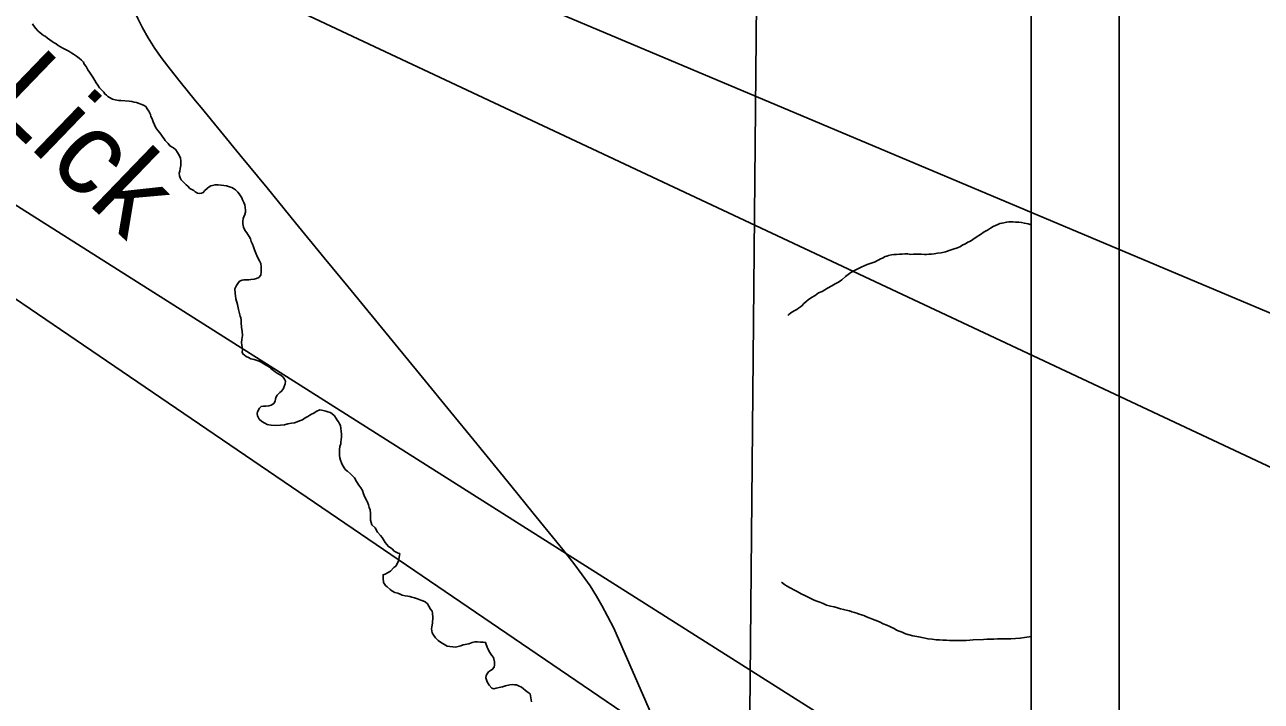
# Model space of a CAD drawing. Extents: x 0 to 34, y 0 to 22.
# Drawn here: x 7.757 to 9.161, y 15.487 to 16.256 of the extents above; entities that cross this region are included whole.
import ezdxf

# ---------------------------------------------------------------- set-up
doc = ezdxf.new("R2010")
doc.units = 0
for name, color, linetype in [('GM_X_County_Text', 7, 'Continuous'), ('GM_X_Minor_River', 7, 'Continuous'), ('GM_X_Minor_River_Text', 7, 'Continuous'), ('GM_X_Rail_Line_Text', 7, 'Continuous'), ('GM_X_State_Route', 7, 'Continuous'), ('SH_Cut_Line', 7, 'Continuous'), ('SH_Data', 7, 'Continuous'), ('TX_P_1', 7, 'Continuous')]:
    doc.layers.add(name, color=color, linetype=linetype)

msp = doc.modelspace()

# ---------------------------------------------------------------- linework, layer by layer
at = {"layer": 'GM_X_County_Text'}
msp.add_lwpolyline([(6.615, 14.1), (8.9, 14.1), (8.9, 16.3981)], dxfattribs=at)
at = {"layer": 'GM_X_Minor_River'}
for points in [[(7.7657, 16.2566), (7.7668, 16.2547), (7.7694, 16.2516), (7.7723, 16.2485), (7.7742, 16.2469), (7.7764, 16.245), (7.7783, 16.2434), (7.7802, 16.2426), (7.7828, 16.2406), (7.788, 16.2367), (7.7902, 16.2351), (7.7925, 16.2339), (7.7947, 16.232), (7.7977, 16.2308), (7.8, 16.2292), (7.8026, 16.228), (7.8048, 16.2268), (7.8071, 16.2256), (7.8105, 16.2233), (7.8123, 16.2224), (7.8157, 16.2201), (7.8187, 16.2177), (7.8213, 16.2154)], [(7.8213, 16.2154), (7.8235, 16.2131), (7.8246, 16.2111), (7.8268, 16.2081), (7.8286, 16.2046), (7.8305, 16.2019), (7.8319, 16.1996), (7.8341, 16.1961), (7.8367, 16.1922), (7.8381, 16.1899), (7.84, 16.1872), (7.8418, 16.1841), (7.8437, 16.1822), (7.8466, 16.1791), (7.8477, 16.1772), (7.8496, 16.1756), (7.8514, 16.174), (7.8533, 16.1732), (7.8567, 16.1713), (7.8597, 16.1704), (7.8635, 16.1696), (7.8661, 16.1695), (7.8756, 16.1689), (7.8786, 16.1685), (7.8813, 16.1676), (7.8839, 16.1672), (7.8869, 16.1664), (7.8888, 16.1656), (7.8918, 16.1643), (7.8945, 16.1628), (7.8959, 16.1601), (7.8977, 16.1574), (7.8996, 16.1539), (7.9003, 16.1516), (7.9014, 16.1497), (7.9021, 16.1478), (7.9028, 16.1455), (7.9042, 16.142), (7.906, 16.1386), (7.9082, 16.1355), (7.9104, 16.1328), (7.9123, 16.1304), (7.9138, 16.1281), (7.9152, 16.1262), (7.9163, 16.1243), (7.9197, 16.1208), (7.9219, 16.118), (7.926, 16.1157), (7.9286, 16.1137), (7.9304, 16.1106), (7.9326, 16.1068), (7.9337, 16.1041), (7.9344, 16.101), (7.9343, 16.098), (7.9343, 16.0957), (7.9334, 16.0923), (7.933, 16.0893), (7.9325, 16.087), (7.9328, 16.084), (7.9335, 16.0817), (7.9346, 16.0794), (7.9372, 16.0767), (7.9402, 16.0739), (7.9421, 16.0724), (7.9446, 16.0696), (7.9469, 16.0684), (7.9488, 16.0673), (7.9506, 16.0657), (7.9533, 16.0645), (7.9555, 16.0641), (7.9578, 16.0644), (7.9597, 16.0651), (7.9613, 16.0673), (7.9644, 16.0699), (7.9663, 16.0714), (7.9683, 16.0725), (7.9702, 16.0732), (7.9732, 16.0739), (7.9766, 16.0738), (7.98, 16.0734), (7.9831, 16.0729), (7.9861, 16.0725), (7.9895, 16.0716), (7.9921, 16.0708), (7.994, 16.0696), (7.9962, 16.068), (7.9988, 16.0653), (8.0003, 16.0634), (8.0036, 16.0591), (8.0043, 16.0568), (8.0058, 16.0538), (8.0069, 16.0511), (8.0072, 16.048), (8.0078, 16.045), (8.0078, 16.0427), (8.007, 16.04), (8.0058, 16.0374), (8.005, 16.0355), (8.0045, 16.0325), (8.0048, 16.0295), (8.0055, 16.0256)], [(8.6242, 15.9252), (8.6246, 15.9259), (8.627, 15.9285), (8.6308, 15.9307), (8.6339, 15.9322), (8.6358, 15.9336), (8.6381, 15.9351), (8.6401, 15.9366), (8.642, 15.9388), (8.6443, 15.941), (8.647, 15.9432), (8.6505, 15.9458), (8.6547, 15.948), (8.6586, 15.9509), (8.6628, 15.9527), (8.6659, 15.9546), (8.6686, 15.9564), (8.6736, 15.9589), (8.6775, 15.9611), (8.6813, 15.9633), (8.6852, 15.9659), (8.6894, 15.9696), (8.6952, 15.974), (8.7018, 15.9777), (8.7071, 15.9802), (8.7106, 15.9816), (8.714, 15.9831), (8.7228, 15.9863), (8.7248, 15.9874), (8.7271, 15.9885), (8.729, 15.9896), (8.7313, 15.9906), (8.7344, 15.9925), (8.7363, 15.9928), (8.7382, 15.9935), (8.7413, 15.9942), (8.7443, 15.9945), (8.7473, 15.9948), (8.7504, 15.9951), (8.7534, 15.9951), (8.7568, 15.9954), (8.7599, 15.9953), (8.7629, 15.9948), (8.7663, 15.9951), (8.7694, 15.9951), (8.772, 15.995), (8.7751, 15.9949), (8.7788, 15.9948), (8.7811, 15.9948), (8.7838, 15.9951), (8.7868, 15.995), (8.7899, 15.9953), (8.7937, 15.996), (8.7979, 15.9967), (8.8028, 15.9977), (8.8082, 15.9995), (8.8128, 16.0009), (8.8166, 16.0023), (8.8197, 16.0037), (8.8224, 16.0056), (8.8254, 16.0066), (8.8281, 16.0085), (8.8312, 16.0099), (8.8339, 16.0118), (8.8378, 16.0143), (8.8424, 16.0173), (8.8466, 16.0202), (8.8505, 16.0224), (8.854, 16.0246), (8.857, 16.0264), (8.8597, 16.0275), (8.8624, 16.0286), (8.8647, 16.0297), (8.867, 16.0304), (8.8723, 16.0314), (8.8746, 16.0317), (8.8769, 16.0316), (8.8792, 16.0316), (8.8822, 16.0315), (8.886, 16.0314), (8.889, 16.031), (8.8924, 16.0301), (8.8966, 16.0293), (8.9, 16.0283)], [(8.0055, 16.0256), (8.0062, 16.0237), (8.0077, 16.021), (8.0091, 16.0191), (8.0102, 16.0172), (8.0117, 16.0149), (8.0132, 16.0126), (8.0142, 16.0095), (8.0157, 16.0064), (8.0167, 16.0034), (8.0178, 15.9999), (8.0196, 15.9961), (8.0214, 15.9915), (8.0236, 15.9876), (8.025, 15.9845), (8.0253, 15.9807), (8.0253, 15.9781), (8.0256, 15.975), (8.0251, 15.9712), (8.0227, 15.9683), (8.0201, 15.9672), (8.0174, 15.9665), (8.0136, 15.9662), (8.0113, 15.9659), (8.0079, 15.9659), (8.006, 15.966), (8.0037, 15.9653), (8.001, 15.9642), (7.9991, 15.9616), (7.9975, 15.9594), (7.9955, 15.9556), (7.9958, 15.9507), (7.9967, 15.9442), (7.9985, 15.9377), (7.9999, 15.9323), (8.0009, 15.9277), (8.0016, 15.9247), (8.0023, 15.9228), (8.0026, 15.9201), (8.0029, 15.9171), (8.0032, 15.9121), (8.0035, 15.9094), (8.0039, 15.9075), (8.0041, 15.9026), (8.0036, 15.898), (8.0032, 15.8946), (8.0035, 15.8916), (8.0038, 15.8893), (8.0041, 15.8866), (8.004, 15.8836), (8.0048, 15.8817), (8.0085, 15.8786), (8.0111, 15.8774), (8.0137, 15.8761), (8.0175, 15.8753), (8.0232, 15.8733), (8.0254, 15.8721), (8.0277, 15.8709), (8.031, 15.8689), (8.0329, 15.8677), (8.0348, 15.8665), (8.0366, 15.865), (8.0396, 15.8626), (8.0415, 15.8614), (8.0437, 15.8599), (8.0456, 15.8587), (8.0479, 15.8575), (8.0505, 15.8551), (8.0519, 15.8528), (8.053, 15.8505), (8.0526, 15.8475), (8.0517, 15.8445), (8.0509, 15.8422), (8.0486, 15.8392), (8.0466, 15.8378), (8.0435, 15.8348), (8.0423, 15.8322), (8.0419, 15.8303), (8.0415, 15.828), (8.0399, 15.8254), (8.0368, 15.8232), (8.0341, 15.8225), (8.0307, 15.8222), (8.028, 15.8222), (8.0254, 15.8219), (8.0234, 15.8201), (8.0214, 15.8159), (8.021, 15.814), (8.0213, 15.8114), (8.0231, 15.8075), (8.0261, 15.8048), (8.0295, 15.8028), (8.0321, 15.8016), (8.034, 15.8012), (8.037, 15.8008), (8.0419, 15.8003), (8.0473, 15.8005), (8.0518, 15.8012), (8.0557, 15.8022), (8.0599, 15.8029), (8.0633, 15.8035)], [(8.0633, 15.8035), (8.0663, 15.8046), (8.069, 15.8057), (8.0725, 15.8068), (8.0756, 15.809), (8.0786, 15.8104), (8.0806, 15.8119), (8.0825, 15.813), (8.0844, 15.8141), (8.0887, 15.8166), (8.0921, 15.8181), (8.0959, 15.8172), (8.0989, 15.8164), (8.1012, 15.8159), (8.1038, 15.8151), (8.1057, 15.8139), (8.1086, 15.8112), (8.1108, 15.8081), (8.1119, 15.8062), (8.1134, 15.8043), (8.1145, 15.8023), (8.1156, 15.8004), (8.1169, 15.7905), (8.1168, 15.7875), (8.1164, 15.7841), (8.1159, 15.7818), (8.1159, 15.7795), (8.115, 15.7765), (8.1146, 15.7731), (8.1145, 15.7693), (8.1144, 15.7662), (8.1147, 15.7636), (8.1154, 15.7609), (8.1169, 15.7578), (8.1176, 15.7559), (8.1198, 15.7521), (8.1216, 15.7497), (8.1235, 15.7482), (8.1268, 15.7454), (8.1291, 15.7431), (8.1313, 15.7408), (8.1338, 15.7365), (8.1364, 15.7323), (8.1386, 15.7296), (8.1404, 15.7265), (8.1419, 15.7227), (8.1426, 15.7207), (8.1437, 15.7181), (8.1451, 15.7154), (8.1462, 15.7131), (8.1473, 15.71), (8.1483, 15.7069), (8.1494, 15.7046), (8.1497, 15.7001), (8.1496, 15.6959), (8.1495, 15.6928), (8.1513, 15.6875), (8.155, 15.684), (8.1575, 15.679), (8.1609, 15.6751), (8.1631, 15.6731), (8.1664, 15.6674), (8.1701, 15.6627), (8.1742, 15.6603), (8.1764, 15.6576), (8.1809, 15.6552), (8.1828, 15.6548), (8.1827, 15.6525), (8.1814, 15.6461), (8.1783, 15.6405), (8.176, 15.639), (8.1725, 15.6349), (8.169, 15.6327), (8.1663, 15.6313), (8.164, 15.6306), (8.1639, 15.6268), (8.1646, 15.6218), (8.1667, 15.6183), (8.1686, 15.6168), (8.172, 15.614), (8.1738, 15.6125), (8.1772, 15.6105), (8.1806, 15.6097), (8.1832, 15.6085), (8.1858, 15.6073), (8.1889, 15.6068), (8.1919, 15.6064), (8.1945, 15.6059), (8.1968, 15.6051), (8.1998, 15.6043), (8.2032, 15.6034), (8.2051, 15.6026), (8.207, 15.6018), (8.2092, 15.601), (8.2119, 15.5998), (8.2145, 15.5975), (8.2159, 15.5951), (8.2177, 15.5917), (8.2196, 15.5894), (8.2199, 15.5871), (8.2206, 15.5821)], [(8.6167, 15.6221), (8.6201, 15.6194), (8.6223, 15.6182), (8.6257, 15.6162), (8.6279, 15.615), (8.6305, 15.6135), (8.6343, 15.6115), (8.6388, 15.6091), (8.6429, 15.6071), (8.6538, 15.6019), (8.6568, 15.6007), (8.6602, 15.5995), (8.664, 15.5979), (8.6677, 15.5962), (8.6723, 15.595), (8.6764, 15.5941), (8.6802, 15.5929), (8.6836, 15.5921), (8.687, 15.5912), (8.69, 15.5904), (8.6938, 15.5895), (8.6964, 15.5887), (8.6994, 15.5879), (8.7021, 15.5871), (8.7047, 15.5859), (8.7073, 15.585), (8.71, 15.5842), (8.713, 15.583), (8.716, 15.5818), (8.7197, 15.5802), (8.7231, 15.579), (8.728, 15.577), (8.7321, 15.575), (8.7363, 15.5733), (8.7397, 15.5717), (8.7419, 15.5706), (8.7445, 15.5694), (8.7472, 15.5678), (8.7502, 15.5666), (8.7536, 15.5653), (8.7573, 15.5637), (8.7615, 15.5625), (8.7656, 15.5613), (8.7724, 15.56), (8.7777, 15.5591), (8.783, 15.5578), (8.7875, 15.5573), (8.7921, 15.5568), (8.7959, 15.5567), (8.7997, 15.5563), (8.8038, 15.5562), (8.8072, 15.5561), (8.8103, 15.556), (8.8137, 15.5559), (8.8183, 15.5558), (8.8224, 15.5561), (8.8262, 15.556), (8.8304, 15.5563), (8.8342, 15.5566), (8.846, 15.5571), (8.8502, 15.5574), (8.854, 15.5576), (8.8578, 15.5576), (8.862, 15.5578), (8.8673, 15.5577), (8.8718, 15.558), (8.8771, 15.5579), (8.8825, 15.5581), (8.8878, 15.5584), (8.8927, 15.5594), (8.8977, 15.56), (8.9, 15.5603)], [(8.2206, 15.5821), (8.22, 15.5757), (8.2192, 15.5715), (8.2191, 15.5692), (8.2198, 15.5647), (8.2216, 15.5616), (8.2234, 15.5589), (8.2264, 15.5561), (8.229, 15.5542), (8.2328, 15.5518), (8.2369, 15.5494), (8.2463, 15.5484), (8.2521, 15.5498), (8.2551, 15.5509), (8.2612, 15.5523), (8.2632, 15.553), (8.2651, 15.5537), (8.2681, 15.5544), (8.2712, 15.5543), (8.2746, 15.5542), (8.2776, 15.5542), (8.2803, 15.5537), (8.2824, 15.5472), (8.2853, 15.5422), (8.2875, 15.5387), (8.2893, 15.5368), (8.2904, 15.5318), (8.2907, 15.5284), (8.2902, 15.5258), (8.2879, 15.5228), (8.286, 15.5217), (8.2836, 15.5202), (8.2821, 15.518), (8.2809, 15.5161), (8.2808, 15.5134), (8.2822, 15.5088), (8.2844, 15.505), (8.2874, 15.5019), (8.2896, 15.5011), (8.2923, 15.5018), (8.2958, 15.5024), (8.2996, 15.5031), (8.303, 15.5046), (8.308, 15.5056), (8.3106, 15.5059), (8.3133, 15.5054), (8.3156, 15.5054), (8.3178, 15.5046), (8.3212, 15.503), (8.3231, 15.5014), (8.3257, 15.4991), (8.3286, 15.4967), (8.3309, 15.4952), (8.3326, 15.4864)]]:
    msp.add_lwpolyline(points, dxfattribs=at)
at = {"layer": 'GM_X_Rail_Line_Text'}
msp.add_lwpolyline([(8.9, 15.3885), (8.9, 16.3968), (8.5987, 16.4027), (8.5893, 16.4029), (8.5798, 15.3924)], close=True, dxfattribs=at)
at = {"layer": 'GM_X_State_Route'}
for points in [[(7.8564, 16.4132), (7.8565, 16.4101), (7.8569, 16.3894), (7.8573, 16.3744), (7.8583, 16.3583), (7.8595, 16.3465), (7.8614, 16.3335), (7.8632, 16.3237), (7.8655, 16.314), (7.8683, 16.3044), (7.8717, 16.2943), (7.8757, 16.2838), (7.8804, 16.2729), (7.8852, 16.2628), (7.8907, 16.2523), (7.8972, 16.2409), (7.9048, 16.2288), (7.913, 16.217), (7.9221, 16.2051), (7.9333, 16.191), (7.951, 16.1693), (7.9573, 16.1616)], [(7.9573, 16.1616), (8.0014, 16.1077), (8.0321, 16.0702), (8.0644, 16.0307), (8.0971, 15.9908), (8.1244, 15.9577), (8.2086, 15.8547), (8.2409, 15.8153), (8.2671, 15.7837), (8.3091, 15.7321), (8.3346, 15.7008), (8.3683, 15.6593), (8.3806, 15.6436), (8.3902, 15.6307), (8.3991, 15.618), (8.4064, 15.6065), (8.4126, 15.5958), (8.419, 15.5837), (8.4259, 15.5698), (8.4898, 15.4241)]]:
    msp.add_lwpolyline(points, dxfattribs=at)
at = {"layer": 'SH_Cut_Line'}
msp.add_lwpolyline([(2.1, 16.5239), (2.1, 14.1), (8.9, 14.1), (8.9, 16.3981)], dxfattribs=at)
at = {"layer": 'SH_Data'}
for p, q in [((9, 21), (9, 14)), ((8.9, 20.9), (8.9, 14.1))]:
    msp.add_line(p, q, dxfattribs=at)
at = {"layer": 'TX_P_1'}
for points in [[(9.2734, 14.9035), (5.5187, 17.4627), (9.2734, 15.0836)], [(9.2734, 15.8853), (5.5318, 17.4627), (9.2734, 15.7052)]]:
    msp.add_lwpolyline(points, close=True, dxfattribs=at)

# ---------------------------------------------------------------- texts
at = {"layer": 'GM_X_Minor_River_Text'}
msp.add_text('Lick', height=0.09475, rotation=316.0476, dxfattribs=at).set_placement((7.7105, 16.1657))

doc.saveas('drawing.dxf')
